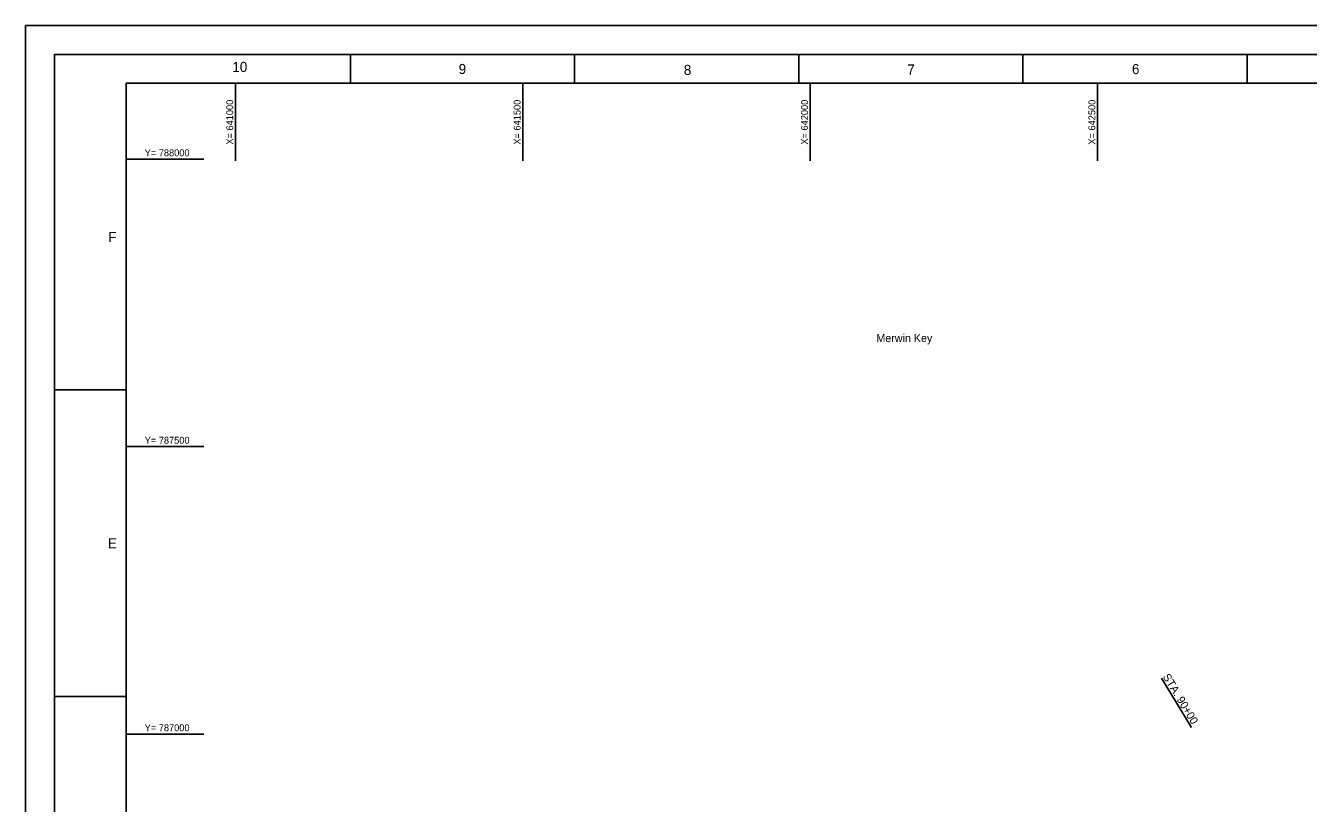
# Model space of a CAD drawing. Extents: x 640635 to 645035, y 784832 to 788232.
# Drawn here: x 640635 to 642867, y 786879 to 788232 of the extents above; entities that cross this region are included whole.
import ezdxf

# ---------------------------------------------------------------- set-up
doc = ezdxf.new("R2010")
doc.units = 0
for name, color, linetype in [('G-ANNO-NPLT', 7, 'Continuous'), ('G-ANNO-TTLB', 7, 'Continuous'), ('V-ALGN-TEXT', 7, 'Continuous'), ('V-SITE-IDEN', 7, 'Continuous'), ('V-TOPO-COOR-STAT', 7, 'Continuous')]:
    doc.layers.add(name, color=color, linetype=linetype)

msp = doc.modelspace()

# ---------------------------------------------------------------- linework, layer by layer
at = {"layer": 'G-ANNO-NPLT'}
msp.add_lwpolyline([(640634.9, 788232.2), (645034.9, 788232.2), (645034.9, 784832.2), (640634.9, 784832.2)], close=True, dxfattribs=at)
msp.add_lwpolyline([(640634.9, 788182.2), (640634.9, 788232.2), (640684.9, 788232.2)], dxfattribs=at)
at = {"layer": 'G-ANNO-TTLB'}
for p, q in [((641199.9, 788182.2), (641199.9, 788132.2)), ((641589.9, 788182.2), (641589.9, 788132.2)), ((641589.9, 788182.2), (641589.9, 788132.2)), ((641979.9, 788182.2), (641979.9, 788132.2)), ((642369.9, 788182.2), (642369.9, 788132.2)), ((642759.9, 788182.2), (642759.9, 788132.2)), ((640684.9, 787598.7), (640809.9, 787598.7)), ((640684.9, 787065.4), (640809.9, 787065.4))]:
    msp.add_line(p, q, dxfattribs=at)
for points in [[(640684.9, 784882.2), (644984.9, 784882.2), (644984.9, 788182.2), (640684.9, 788182.2)], [(644934.9, 788132.2), (640809.9, 788132.2), (640809.9, 784932.2), (644934.9, 784932.2)]]:
    msp.add_lwpolyline(points, close=True, dxfattribs=at)
at = {"layer": 'V-ALGN-TEXT'}
msp.add_line((642611.1, 787097.1), (642663.1, 787011.6), dxfattribs=at)
at = {"layer": 'V-TOPO-COOR-STAT'}
for p, q in [((641000, 787997.2), (641000, 788132.2)), ((641500, 787997.2), (641500, 788132.2)), ((642000, 787997.2), (642000, 788132.2)), ((642500, 787997.2), (642500, 788132.2)), ((640809.9, 788000), (640944.9, 788000)), ((640809.9, 787500), (640944.9, 787500)), ((640809.9, 787000), (640944.9, 787000))]:
    msp.add_line(p, q, dxfattribs=at)

# ---------------------------------------------------------------- texts
at = {"layer": 'G-ANNO-TTLB'}
for s, p in [('10', (640994.5, 788151.7)), ('9', (641388.3, 788148.1)), ('8', (641780, 788146.5)), ('7', (642168.8, 788147.2)), ('6', (642559.7, 788147.9)), ('F', (640778.5, 787855.8)), ('E', (640778.3, 787323.1))]:
    msp.add_text(s, height=17.5, dxfattribs=at).set_placement(p)
at = {"layer": 'V-ALGN-TEXT'}
msp.add_text('STA. 90+00', height=13.92, rotation=301.2715, dxfattribs=at).set_placement((642612.7, 787099.9))
at = {"layer": 'V-SITE-IDEN'}
msp.add_text('Merwin Key', height=13.92, dxfattribs=at).set_placement((642115.1, 787681.8))
at = {"layer": 'V-TOPO-COOR-STAT'}
for s, p in [('X= 641000', (640996, 788025.3)), ('X= 641500', (641496, 788025.3)), ('X= 642000', (641996, 788025.3)), ('X= 642500', (642496, 788025.3))]:
    msp.add_text(s, height=12, rotation=90, dxfattribs=at).set_placement(p)
for s, p in [('Y= 788000', (640842, 788005)), ('Y= 787500', (640842, 787505)), ('Y= 787000', (640842, 787005))]:
    msp.add_text(s, height=12, dxfattribs=at).set_placement(p)

doc.saveas('drawing.dxf')
